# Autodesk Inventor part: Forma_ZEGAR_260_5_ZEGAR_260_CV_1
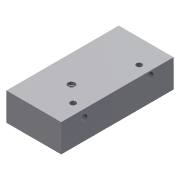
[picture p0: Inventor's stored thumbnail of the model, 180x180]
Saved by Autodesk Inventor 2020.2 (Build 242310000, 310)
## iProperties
Created: 2015-01
Part Number: Forma_ZEGAR_260_5_ZEGAR_260_CV_1
Material: Ogólny
Document SubType Name: Modeling
Designer: F.Stasiak
Density: 1 g/cm^3
Appearance: Domyślna
Catalog Web Link: www.expertbooks.pl
Manager: www.cadconsulting.pl
Company: Fabian Stasiak CAD Consulting
Author: F.Stasiak
Subject: Zbiór ćwiczeń. Autodesk Inventor 2020. Kurs Professional
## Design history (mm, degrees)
node "Forma_ZEGAR_260_4_ZEGAR_260_CV_Base"
feature "Rzeźbienie4"
feature "Gwint1" dims "d6" = 0, "d7" = 0
feature "Rzeźbienie7"
feature "Gwint4" dims "d12" = 0, "d13" = 0
feature "Rzeźbienie9"
feature "Rzeźbienie12"
feature "Bryła1::Forma_ZEGAR_260_4_ZEGAR_260_CV_Base"
tag "Bryła wyprowadzona1"
node "Bryła1"
feature "Forma_ZEGAR_260_4_ZEGAR_260_CV_Base_Bodies"
feature "Powierzchnia4"
body "Srf4"
feature "Powierzchnia7"
body "Srf7"
feature "Powierzchnia9"
body "Srf9"
feature "Powierzchnia12"
body "Srf12"
other parameters: "d0" = 0, "d1" = -26.4075, "d3" = 0, "d4" = -180 deg, "d5" = 0
